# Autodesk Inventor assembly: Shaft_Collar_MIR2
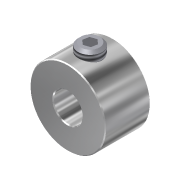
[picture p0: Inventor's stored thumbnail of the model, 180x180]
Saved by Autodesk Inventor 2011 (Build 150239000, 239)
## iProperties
Created: 2008-03
Part Number: Shaft_Collar_MIR2
Document SubType Name: Assembly
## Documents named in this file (3)
- C:\Data Folder\VEX 2011\Inventor Datasets\Unit 16\Components\Shaft_Collar_MIR2.iam
- C:\Data Folder\VEX 2011\Inventor Datasets\Unit 16\Components\SHAFT-COLLAR_MIR2.ipt
- C:\Data Folder\VEX 2011\Inventor Datasets\Unit 16\Content Center\en-US\ANSI B18.3(08)\ANSI B18.3 - 6-40 UNF - 0.188(24).ipt
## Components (2 placed, 2 different names)
1. SHAFT-COLLAR_MIR2:1 — Mate:2
2. Hexagon Socket Set Screw - Flat Point - Inch 6-40 UNF x 0.188:1 — Flush:2, Mate:2
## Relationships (2: Flush 1, Mate 1)
- Flush:2: Hexagon Socket Set Screw - Flat Point - Inch 6-40 UNF x 0.188:1
- Mate:2: SHAFT-COLLAR_MIR2:1 ↔ Hexagon Socket Set Screw - Flat Point - Inch 6-40 UNF x 0.188:1
